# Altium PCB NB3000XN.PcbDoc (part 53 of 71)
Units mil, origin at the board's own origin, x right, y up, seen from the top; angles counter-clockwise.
Board outline 9527.56 x 6929.77 mil, 6 copper layers (Top Layer, GND+SHIELD, MidLayer1, MidLayer2, P2 - 3V3+5V0, Bottom Layer), stack 62.375 mil thick; 832 components, 1027 nets, 4655 pads, 4981 vias.
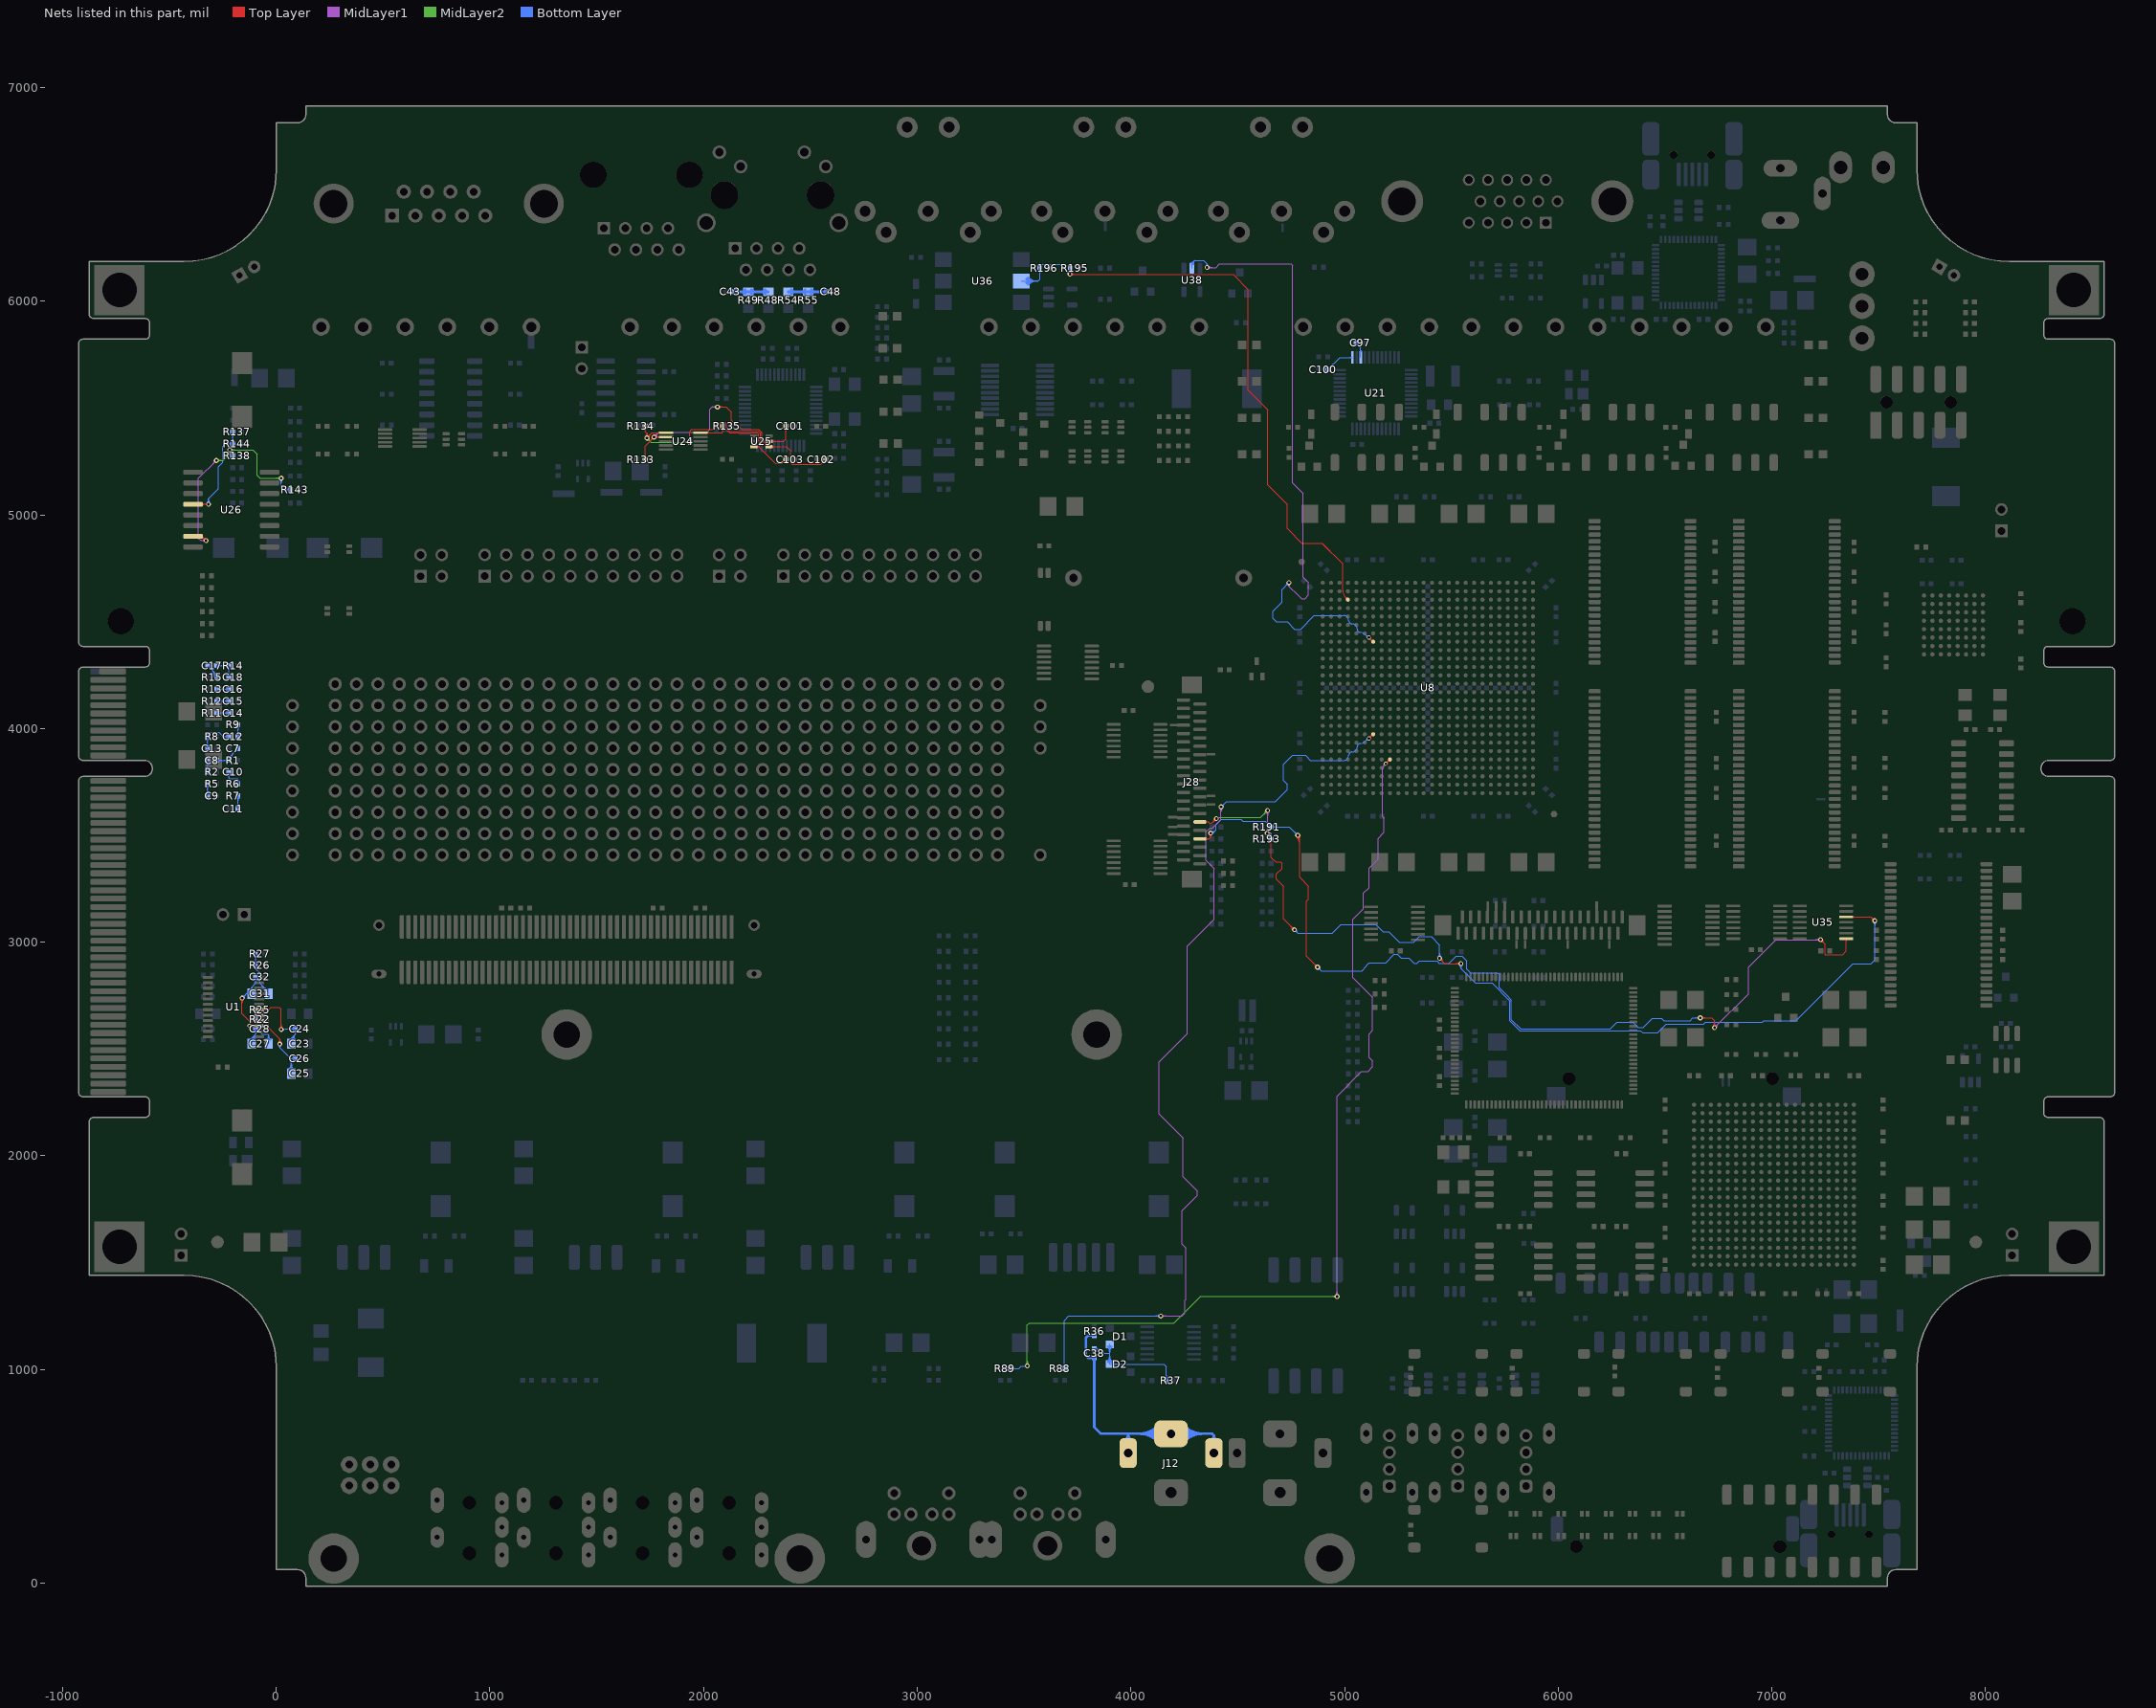
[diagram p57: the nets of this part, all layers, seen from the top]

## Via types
v1: diameter 23, hole 11.81, Top Layer to Bottom Layer, 3672 vias
v2: diameter 26, hole 11.81, Top Layer to Bottom Layer, 461 vias
v3: diameter 19, hole 11.81, Top Layer to Bottom Layer, tented both sides, 396 vias
v4: diameter 23.62, hole 11.81, Top Layer to Bottom Layer, 288 vias
v5: diameter 20, hole 11.81, Top Layer to Bottom Layer, 91 vias
v6: diameter 23, hole 11.81, Top Layer to Bottom Layer, tented both sides, 50 vias
v7: diameter 31, hole 11.81, Top Layer to Bottom Layer, 15 vias
v8: diameter 27.56, hole 11.81, Top Layer to Bottom Layer, tented both sides, 4 vias
v9: diameter 29, hole 11.81, Top Layer to Bottom Layer, 3 vias
v10: diameter 21, hole 11.81, Top Layer to Bottom Layer, 1 vias

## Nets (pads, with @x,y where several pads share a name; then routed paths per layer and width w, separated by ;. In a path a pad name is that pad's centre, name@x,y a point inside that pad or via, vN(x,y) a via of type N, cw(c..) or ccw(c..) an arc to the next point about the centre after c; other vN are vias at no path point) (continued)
LEDS#.LED7.GREEN: J28.30 R193.2 U35.12 | length 5428
  Top Layer w4: J28.30@4323.39,3562.99 4361.19,3562.99 4367.34,3556.84 4378.66,3556.84 v1(4400.52,3578.71) ; J28.30@4349.67,3558.84 cw(c4359.69,3548.81) 4359.69,3562.99 cw(c4359.69,3577.17) J28.30@4349.67,3567.15 ; v1@4391.02,3578.71 cw(c4368.09,3578.71) 4384.31,3562.49 cw(c4400.52,3546.27) v1@4400.52,3569.21 ; v1@4395.02,3578.71 cw(c4381.75,3578.71) 4391.14,3569.32 cw(c4400.52,3559.93) v1@4400.52,3573.21 ; v1@4637.52,3501.54 cw(c4637.52,3478.61) 4653.74,3494.82 cw(c4669.96,3511.04) v1@4647.02,3511.04 ; v1@4637.52,3505.54 cw(c4637.52,3492.26) 4646.91,3501.65 cw(c4656.3,3511.04) v1@4643.02,3511.04 ; v1(4637.52,3511.04) 4657.19,3491.37 4657.19,3396.73 4678.88,3375.04 4700.9,3375.04 4706.86,3369.08 4706.86,3345.37 4681.86,3320.37 4681.86,3296.04 4715.19,3262.71 4715.19,3108.37 v1(4765.19,3058.37) ; v1@4755.69,3058.37 ccw(c4732.76,3058.37) 4748.97,3074.59 ccw(c4765.19,3090.81) v1@4765.19,3067.87 ; v1@4759.69,3058.37 ccw(c4746.41,3058.37) 4755.8,3067.76 ccw(c4765.19,3077.15) v1@4765.19,3063.87 ; v1@5445,2915.5 cw(c5445,2893.02) 5460.9,2908.92 ; v1@5445,2919.5 cw(c5445,2906.68) 5454.07,2915.74 ; v1(5445,2925) 5445,2924.81 5469.77,2900.04 v1(5544.52,2900.04) ; v1@5450.5,2925 ccw(c5464.23,2925) 5454.52,2915.29 ; v1@5454.5,2925 ccw(c5477.89,2925) 5461.35,2908.46 ; v1@5537.81,2893.32 ccw(c5521.59,2877.11) 5521.59,2900.04 ccw(c5521.59,2922.98) v1@5537.81,2906.76 ; v1@5540.64,2896.15 ccw(c5531.25,2886.76) 5531.25,2900.04 ccw(c5531.25,2913.32) v1@5540.64,2903.93 ; U35.12@7348.5,3118.82 7463.75,3118.82 v1(7481.86,3100.71) ; U35.12@7377.81,3115.99 cw(c7384.64,3109.16) 7384.64,3118.82 cw(c7384.64,3128.48) U35.12@7377.81,3121.65 ; v1@7472.36,3100.71 ccw(c7449.42,3100.71) 7465.64,3116.93 ccw(c7481.86,3133.14) v1@7481.86,3110.21 ; v1@7476.36,3100.71 ccw(c7463.08,3100.71) 7472.47,3110.1 ccw(c7481.86,3119.49) v1@7481.86,3106.21
  MidLayer1 w4: v1@4630.81,3517.76 ccw(c4608.15,3540.41) 4640.19,3540.41 ; v1@4633.47,3609.99 cw(c4617.26,3593.77) 4640.19,3593.77 cw(c4663.13,3593.77) v1@4646.91,3609.99 ; v1@4633.64,3514.93 ccw(c4617.81,3530.76) 4640.19,3530.76 ; v1@4636.3,3612.82 cw(c4626.91,3603.43) 4640.19,3603.43 cw(c4653.47,3603.43) v1@4644.08,3612.82 ; v1(4637.52,3511.04) 4640.19,3513.71 v1(4640.19,3616.71) ; 4640.19,3527.54 ccw(c4654.02,3527.54) v1@4644.24,3517.76
  MidLayer2 w4: v1(4400.52,3578.71) 4405.19,3583.37 4606.86,3583.37 v1(4640.19,3616.71) ; v1@4630.69,3616.71 cw(c4607.76,3616.71) 4623.97,3600.49 cw(c4640.19,3584.27) v1@4640.19,3607.21 ; v1@4634.69,3616.71 cw(c4621.41,3616.71) 4630.8,3607.32 cw(c4640.19,3597.93) v1@4640.19,3611.21
  Bottom Layer w4: v1(4637.52,3511.04) 4654.19,3511.04 ; v1@4645.7,3506.2 cw(c4654.19,3501.17) 4654.19,3511.04 ; v1@4645.7,3515.88 ccw(c4654.19,3520.91) 4654.19,3511.04 ; R193.2@4649.59,3490.21 ccw(c4633.68,3506.12) 4656.18,3506.12 ccw(c4678.68,3506.11) R193.2@4662.77,3490.21 ; R193.2@4652.42,3487.38 ccw(c4643.34,3496.46) 4656.18,3496.46 ccw(c4669.02,3496.46) R193.2@4659.94,3487.38 ; R193.2@4656.18,3483.12 4656.18,3509.05 4654.19,3511.04 ; v1@4765.19,3048.87 cw(c4765.19,3025.94) 4781.41,3042.16 cw(c4797.63,3058.37) v1@4774.69,3058.37 ; v1@4765.19,3052.87 cw(c4765.19,3039.6) 4774.58,3048.99 cw(c4783.97,3058.37) v1@4770.69,3058.37 ; v1(4765.19,3058.37) 4781.86,3041.71 4941.9,3041.71 4983.56,3083.37 5146.54,3083.37 5179.88,3050.04 5206.86,3050.04 5256.86,3000.04 5323.52,3000.04 5341.48,3018 5349.36,3025.87 5405.77,3025.87 5445,2986.65 v1(5445,2925) ; v1@5438.28,2931.72 ccw(c5422.06,2947.93) 5445,2947.93 ccw(c5467.93,2947.93) v1@5451.72,2931.72 ; v1@5441.11,2928.89 ccw(c5431.72,2938.28) 5445,2938.28 ccw(c5458.28,2938.28) v1@5448.89,2928.89 ; v1@5537.81,2893.32 cw(c5521.59,2877.11) 5544.52,2877.11 cw(c5567.46,2877.11) v1@5551.24,2893.32 ; v1@5540.64,2896.15 cw(c5531.25,2886.76) 5544.52,2886.76 cw(c5557.8,2886.76) v1@5548.41,2896.15 ; v1(5544.52,2900.04) 5544.52,2875.48 5611.63,2808.37 5690.19,2808.37 5773.52,2725.04 5773.52,2633.37 5821.19,2585.71 6385.48,2585.71 6395.48,2575.71 6445,2575.71 6465.86,2575.71 6506.86,2616.71 6680.52,2616.71 6690.19,2626.37 6956.94,2626.37 6963.94,2633.37 7112.21,2633.37 7378.88,2900.04 7465.19,2900.04 7481.86,2916.71 v1(7481.86,3100.71) ; v1@7475.14,3093.99 cw(c7458.92,3077.77) 7481.86,3077.77 cw(c7504.79,3077.77) v1@7488.57,3093.99 ; v1@7477.97,3096.82 cw(c7468.58,3087.43) 7481.86,3087.43 cw(c7495.14,3087.43) v1@7485.75,3096.82
LEDS#.LED7.RED: J28.34 R191.2 U35.8 | length 5342.9
  Top Layer w4: J28.34@4323.39,3484.25 4365.52,3484.25 4373.52,3492.25 ; J28.34@4349.67,3480.1 cw(c4359.69,3470.07) 4359.69,3484.25 cw(c4359.69,3498.43) J28.34@4349.67,3488.41 ; v1@4367.89,3503.39 cw(c4359.7,3492.25) 4373.52,3492.25 ; v1(4373.52,3511.04) 4373.52,3492.25 ; v1@4379.16,3503.39 ccw(c4387.35,3492.25) 4373.52,3492.25 ; v1@4775.14,3493.32 cw(c4738.8,3456.99) 4790.19,3456.99 ; v1@4777.97,3496.15 cw(c4748.46,3466.64) 4790.19,3466.64 ; v1@4780.8,3498.98 cw(c4758.12,3476.3) 4790.19,3476.3 ; v1(4781.86,3500.04) 4790.19,3491.71 4790.19,3304.02 4831.52,3262.69 4831.52,3201.69 4822.86,3193.02 4822.86,2934.04 v1(4873.52,2883.37) ; v1@4783.62,3501.81 cw(c4767.78,3485.96) 4790.19,3485.96 ; v1@4864.02,2883.37 ccw(c4841.09,2883.37) 4857.31,2899.59 ccw(c4873.52,2915.81) v1@4873.52,2892.87 ; v1@4868.02,2883.37 ccw(c4854.75,2883.37) 4864.14,2892.76 ccw(c4873.52,2902.15) v1@4873.52,2888.87 ; v1(6665.19,2645.71) 6719.29,2645.71 6731.86,2633.14 v1(6731.86,2600.04) ; v1@6669.08,2641.82 cw(c6678.47,2632.43) 6678.47,2645.71 cw(c6678.47,2658.99) v1@6669.08,2649.6 ; v1@6671.91,2638.99 cw(c6688.13,2622.77) 6688.13,2645.71 cw(c6688.13,2668.64) v1@6671.91,2652.43 ; v1@6725.14,2606.76 ccw(c6708.92,2622.98) 6731.86,2622.98 ccw(c6754.79,2622.98) v1@6738.57,2606.76 ; v1@6727.97,2603.93 ccw(c6718.58,2613.32) 6731.86,2613.32 ccw(c6745.14,2613.32) v1@6735.75,2603.93 ; v1@7228.19,3002.54 cw(c7228.19,2979.61) 7244.41,2995.82 cw(c7260.63,3012.04) v1@7237.69,3012.04 ; v1@7228.19,3006.54 cw(c7228.19,2993.26) 7237.58,3002.65 cw(c7246.97,3012.04) v1@7233.69,3012.04 ; v1(7228.19,3012.04) 7248.52,2991.71 7248.52,2943.37 7250.19,2941.71 7331.86,2941.71 7348.52,2958.37 U35.8@7348.5,3016.46 ; U35.8@7345.68,3013.63 cw(c7338.8,3006.75) 7348.52,3006.75 ; 7348.52,3006.85 cw(c7358.11,3006.85) U35.8@7351.33,3013.63 ; U35.8@7348.5,3016.46 7348.52,3016.71 U35.8@7348.5,3016.46
  MidLayer1 w4: v1(6731.86,2600.04) 6890.19,2758.37 6890.19,2882.77 7019.46,3012.04 v1(7228.19,3012.04) ; v1@6731.86,2605.54 ccw(c6731.86,2618.82) 6741.25,2609.43 ccw(c6750.64,2600.04) v1@6737.36,2600.04 ; v1@6731.86,2609.54 ccw(c6731.86,2632.48) 6748.07,2616.26 ccw(c6764.29,2600.04) v1@6741.36,2600.04 ; v1@7221.47,3005.32 ccw(c7205.26,2989.11) 7205.26,3012.04 ccw(c7205.26,3034.98) v1@7221.47,3018.76 ; v1@7224.3,3008.15 ccw(c7214.91,2998.76) 7214.91,3012.04 ccw(c7214.91,3025.32) v1@7224.3,3015.93
  Bottom Layer w4: v1(4373.52,3511.04) 4384.52,3511.04 4398.52,3525.04 ; v1@4374.02,3512.46 ccw(c4378.92,3526.59) 4389.5,3516.01 ; v1@4375.33,3516.24 ccw(c4381.25,3533.29) 4394.01,3520.53 ; v1@4376.64,3520.02 ccw(c4383.57,3539.99) 4398.52,3525.04 ; 4639.43,3556.75 ccw(c4656.18,3573.5) R191.2@4656.18,3549.81 ; 4640.62,3555.56 cw(c4625.55,3540.49) R191.2@4646.86,3540.49 ; R191.2@4646.26,3549.92 ccw(c4656.18,3559.84) R191.2@4656.18,3545.81 ; R191.2@4647.45,3548.73 cw(c4639.21,3540.49) R191.2@4650.86,3540.49 ; R191.2@4659.94,3536.24 cw(c4669.02,3527.16) 4669.02,3540 cw(c4669.02,3552.84) R191.2@4659.94,3543.76 ; R191.2@4662.77,3533.41 cw(c4678.68,3517.5) 4678.68,3540 cw(c4678.68,3562.5) R191.2@4662.77,3546.59 ; v1@4772.36,3500.04 ccw(c4749.42,3500.04) 4765.64,3516.26 ccw(c4781.86,3532.48) v1@4781.86,3509.54 ; v1@4776.36,3500.04 ccw(c4763.08,3500.04) 4772.47,3509.43 ccw(c4781.86,3518.82) v1@4781.86,3505.54 ; v1(4781.86,3500.04) 4741.9,3540 R191.2@4656.18,3540 4629.47,3566.71 4523.52,3566.71 4515.19,3575.04 4423.52,3575.04 4398.52,3550.04 4398.52,3525.04 ; v1@4873.52,2873.87 cw(c4873.52,2850.94) 4889.74,2867.16 cw(c4905.96,2883.37) v1@4883.02,2883.37 ; v1@4873.52,2877.87 cw(c4873.52,2864.6) 4882.91,2873.99 cw(c4892.3,2883.37) v1@4879.02,2883.37 ; v1(4873.52,2883.37) 4890.52,2866.37 5081.56,2866.37 5102.81,2887.62 5102.81,2891.1 5114.52,2902.81 5192.62,2902.81 5232.62,2942.81 5247.38,2942.81 5265.31,2924.88 5302.27,2924.88 5325.61,2901.54 5340.11,2901.54 5350.36,2911.79 5433.46,2911.79 5443.06,2902.19 5489.36,2902.19 5522.17,2935 5550,2935 5573.19,2911.81 5573.19,2874.04 5589.86,2857.37 5716.19,2857.37 5723.52,2850.04 5723.52,2786.37 5757.18,2752.72 5781.52,2728.37 5781.52,2636.69 5824.5,2593.71 6243.19,2593.71 6274.52,2625.04 6348.52,2625.04 6373.52,2600.04 6398.52,2600.04 6441.86,2643.37 6442.69,2644.2 6484.34,2644.2 6495.5,2633.04 6617.33,2633.04 6630,2645.71 v1(6665.19,2645.71) ; v1@6658.47,2638.99 ccw(c6642.26,2622.77) 6642.26,2645.71 ccw(c6642.26,2668.64) v1@6658.47,2652.43 ; v1@6661.3,2641.82 ccw(c6651.91,2632.43) 6651.91,2645.71 ccw(c6651.91,2658.99) v1@6661.3,2649.6
LINEAOUT_L: R137.2 R144.1 U26.4 | length 757.1
  Top Layer w4: U26.4@-389.13,5050 -332.81,5050 ; U26.4@-351.46,5046 cw(c-342.13,5037.13) -342.13,5050 cw(c-342.13,5062.87) U26.4@-351.46,5054 ; U26.4@-348.56,5043.24 cw(c-332.81,5028.28) -332.81,5050 ; U26.4@-348.56,5056.76 ccw(c-332.81,5071.72) -332.81,5050 ; -332.77,5050.04 v1(-317.14,5050.04)
  Bottom Layer w4: v1@-323.86,5056.76 ccw(c-340.08,5072.98) -317.14,5072.98 ccw(c-294.21,5072.98) v1@-310.43,5056.76 ; v1@-321.03,5053.93 ccw(c-330.42,5063.32) -317.14,5063.32 ccw(c-303.86,5063.32) v1@-313.25,5053.93 ; v1(-317.14,5050.04) -317.14,5075 -270,5122.14 -270,5225 -250,5245 -250,5320 -237.42,5332.58 R144.1@-203.21,5332.58 R137.2@-203.21,5388.42 ; R144.1@-209.8,5325.99 ccw(c-225.71,5310.08) -225.71,5332.58 ccw(c-225.71,5355.08) R144.1@-209.8,5339.17 ; R144.1@-209.8,5339.66 ccw(c-225.71,5355.57) -203.21,5355.57 ccw(c-180.71,5355.57) R144.1@-196.62,5339.66 ; R137.2@-209.8,5381.33 cw(c-225.71,5365.43) -203.21,5365.43 cw(c-180.71,5365.43) R137.2@-196.62,5381.33 ; R144.1@-206.97,5328.82 ccw(c-216.05,5319.74) -216.05,5332.58 ccw(c-216.05,5345.42) R144.1@-206.97,5336.34 ; R144.1@-206.97,5336.84 ccw(c-216.05,5345.91) -203.21,5345.91 ccw(c-190.37,5345.91) R144.1@-199.45,5336.84 ; R137.2@-206.97,5384.16 cw(c-216.05,5375.08) -203.21,5375.08 cw(c-190.37,5375.08) R137.2@-199.45,5384.16
LINEAOUT_R: R138.2 R143.1 U26.7 | length 1685.2
  Top Layer w4: U26.7@-395,4900 U26.7@-389.13,4900 -348,4900 v1(-328,4880) ; U26.7@-355.67,4894.19 cw(c-355.67,4861.64) v1@-332.66,4884.66 ; U26.7@-355.67,4898.19 cw(c-355.67,4875.3) -339.49,4891.49 ; U26.7@-345.86,4900 ccw(c-340.69,4900) U26.7@-344.34,4896.34 ; v1@-337.5,4880 ccw(c-360.44,4880) -344.22,4896.22 ccw(c-328,4912.43) v1@-328,4889.5 ; v1@-333.5,4880 ccw(c-346.78,4880) -337.39,4889.39 ccw(c-328,4898.78) v1@-328,4885.5
  MidLayer1 w4: v1@-334.72,4873.28 ccw(c-350.94,4857.06) -350.94,4880 ccw(c-350.94,4902.93) v1@-334.72,4886.72 ; v1@-331.89,4876.11 ccw(c-341.28,4866.72) -341.28,4880 ccw(c-341.28,4893.28) v1@-331.89,4883.89 ; v1(-328,4880) -354,4880 -364,4890 -364,5171 v1(-280,5255) ; v1@-289.5,5255 cw(c-312.44,5255) -296.22,5238.78 cw(c-280,5222.56) v1@-280,5245.5 ; v1@-285.5,5255 cw(c-298.78,5255) -289.39,5245.61 cw(c-280,5236.22) v1@-280,5249.5
  MidLayer2 w4: v1(-280,5255) -248.14,5255 -217.81,5285.33 ; v1@-276.11,5251.11 cw(c-266.72,5241.72) -266.72,5255 cw(c-266.72,5268.28) v1@-276.11,5258.89 ; v1@-273.28,5248.28 cw(c-257.07,5232.06) -257.07,5255 cw(c-257.07,5277.93) v1@-273.28,5261.72 ; v1@-223.52,5296.78 cw(c-232.14,5285.33) -217.81,5285.33 ; v1@-213.92,5300.49 cw(c-204.53,5291.1) -204.53,5304.37 cw(c-204.53,5317.65) v1@-213.92,5308.26 ; v1@-212.1,5296.78 ccw(c-203.48,5285.33) -217.81,5285.33 ; v1@-211.09,5297.66 cw(c-194.87,5281.44) -194.87,5304.37 cw(c-194.87,5327.31) v1@-211.09,5311.09 ; v1@16.81,5164.99 ccw(c0.59,5148.77) 0.59,5171.71 ccw(c0.59,5194.64) v1@16.81,5178.43 ; v1@19.64,5167.82 ccw(c10.25,5158.43) 10.25,5171.71 ccw(c10.25,5184.99) v1@19.64,5175.6 ; v1(23.52,5171.71) -76.71,5171.71 -90,5185 -90,5284.37 -110,5304.37 v1(-217.81,5304.37) -217.81,5285.33
  Bottom Layer w4: v1@-218.11,5304.67 cw(c-241.69,5281.09) R138.2@-208.5,5277.77 ; v1(-217.81,5304.37) -203.21,5289.77 R138.2@-203.21,5276.75 ; v1@-212.14,5298.7 cw(c-230.84,5280) R138.2@-204.52,5277.37 ; -206.17,5292.73 cw(c-219.98,5278.92) R138.2@-200.54,5276.97 ; v1@16.81,5164.99 cw(c0.59,5148.77) 23.52,5148.77 cw(c46.46,5148.77) v1@30.24,5164.99 ; v1@19.64,5167.82 cw(c10.25,5158.43) 23.52,5158.43 cw(c36.8,5158.43) v1@27.41,5167.82 ; v1(23.52,5171.71) 23.52,5128.65 33.52,5118.65 R143.1@66.28,5118.65 ; R143.1@59.69,5112.06 ccw(c43.78,5096.16) 43.78,5118.65 ccw(c43.78,5141.15) R143.1@59.69,5125.24 ; R143.1@62.52,5114.89 ccw(c53.44,5105.81) 53.44,5118.65 ccw(c53.44,5131.5) R143.1@62.52,5122.41
MIDI.MIDI_RX: R195.1 R196.2 U8.C4 U36.5 | length 3637.6
  Top Layer w4: v1(3715.19,6127.37) 3717.52,6125.04 4425,6125.04 4459.96,6125.04 4478.88,6125.04 4548.52,6055.39 4548.52,5708.37 4548.52,5695 4548.52,5583.37 4640.19,5491.71 4640.19,5140.71 4731.86,5049.04 4731.86,4936.35 4800.5,4867.71 4894.79,4867.71 ; v1@3719.08,6131.26 ccw(c3734.1,6146.29) 3734.1,6125.04 ; v1@3721.91,6120.66 cw(c3732.49,6110.07) 3732.49,6125.04 ; v1@3721.91,6134.09 ccw(c3743.76,6155.94) 3743.76,6125.04 ; 4931.61,4831.02 4894.92,4867.71 4894.79,4867.71 ; 4894.79,4867.71 4896.29,4866.21 4896.42,4866.21 4992.12,4770.51 4992.12,4724.74 4992.12,4720 4992.12,4710 4992.12,4643.27 ; 4992.12,4643.27 ccw(c5030.8,4643.27) 5003.45,4615.92 ; 4992.12,4643.27 ccw(c5030.8,4643.27) 5003.45,4615.92 ; 5003.45,4615.92 cw(c4990.92,4603.39) 5008.64,4603.39 ccw(c4990.92,4603.39) 5003.45,4615.92 ; 5003.45,4615.92 ccw(c5015.98,4628.45) 5015.98,4610.73 cw(c5015.98,4628.45) 5003.45,4615.92
  Bottom Layer w4: U36.5@3487.48,6095 3565.19,6095 ; U36.5@3505.28,6083.81 cw(c3529.93,6062.24) 3529.93,6095 cw(c3529.94,6127.76) U36.5@3505.28,6106.19 ; U36.5@3508.29,6081.17 cw(c3538.75,6054.53) 3538.75,6095 cw(c3538.75,6135.47) U36.5@3508.29,6108.83 ; U36.5@3511.3,6078.54 cw(c3547.56,6046.82) 3547.56,6095 cw(c3547.56,6143.18) U36.5@3511.3,6111.46 ; U36.5@3514.31,6075.91 cw(c3556.37,6039.12) 3556.37,6095 cw(c3556.37,6150.89) U36.5@3514.31,6114.09 ; U36.5@3517.32,6073.27 cw(c3565.19,6031.41) 3565.19,6095 ; U36.5@3517.32,6116.73 ccw(c3565.19,6158.59) 3565.19,6095 ; R196.2@3567.23,6147.92 cw(c3551.32,6132.01) 3573.82,6132.01 cw(c3596.32,6132.01) R196.2@3580.41,6147.92 ; R196.2@3569.13,6163.54 ccw(c3564.37,6171.71) 3573.82,6171.71 ; R196.2@3570.06,6150.75 cw(c3560.98,6141.67) 3573.82,6141.67 cw(c3586.66,6141.67) R196.2@3577.58,6150.75 ; R196.2@3578.51,6163.54 cw(c3583.27,6171.71) 3573.82,6171.71 ; v1@3705.69,6127.37 ccw(c3682.76,6127.37) 3698.97,6143.59 ccw(c3715.19,6159.81) v1@3715.19,6136.87 ; v1@3709.69,6127.37 ccw(c3696.41,6127.37) 3705.8,6136.76 ccw(c3715.19,6146.15) v1@3715.19,6132.87 ; R195.1@3713.04,6145.79 cw(c3711.25,6141.04) 3716.32,6141.04 ; R195.1@3716.32,6155 3716.32,6141.04 ; R195.1@3719.6,6145.79 ccw(c3721.39,6141.04) 3716.32,6141.04 ; 3565.19,6095 3573.82,6103.63 3573.82,6171.71 ; 3573.82,6171.71 3575.49,6173.37 3669.19,6173.37 v1(3715.19,6127.37) 3715.19,6139.91 3716.32,6141.04
MIDI.MIDI_TX: U8.H7 U38.2 | length 3354
  Top Layer w4: v3(5114.41,4426.22) U8.H7@5134.09,4406.54 ; U8.H7@5126.59,4406.54 ccw(c5108.49,4406.54) 5121.29,4419.34 ccw(c5134.09,4432.14) U8.H7@5134.09,4414.04 ; U8.H7@5126.75,4406.54 ccw(c5109.03,4406.54) 5121.56,4419.07 ccw(c5134.09,4431.6) U8.H7@5134.09,4413.88 ; 5127.21,4413.42 ccw(c5114.41,4400.61) 5114.41,4418.72 cw(c5114.41,4400.61) 5127.21,4413.42 ; 5127.21,4413.42 cw(c5140.02,4426.22) 5121.91,4426.22 ccw(c5140.02,4426.22) 5127.21,4413.42
  MidLayer1 w4: v1(4356.86,6158.37) 4398.37,6158.37 4415.37,6175.37 4750,6175.37 ; v1@4360.75,6154.49 cw(c4370.14,6145.1) 4370.14,6158.37 cw(c4370.14,6171.65) v1@4360.75,6162.26 ; v1@4363.57,6151.66 cw(c4379.79,6135.44) 4379.79,6158.37 cw(c4379.79,6181.31) v1@4363.57,6165.09 ; v1@4735.35,4675.2 cw(c4730.32,4666.71) 4740.19,4666.71 ; v1(4740.19,4683.37) 4740.19,4666.71 ; v1@4745.03,4675.2 ccw(c4750.06,4666.71) 4740.19,4666.71 ; 4750,6175 4757.69,6167.31 4757.69,5149.21 4806.86,5100.04 4806.86,4708.37 4831.86,4683.37 4831.86,4625.04 4815.19,4608.37 4798.52,4608.37 4781.86,4625.04 4740.19,4666.71
  Bottom Layer w4: U38.2@4285.84,6155.12 U38.2@4285.84,6168.71 ; U38.2@4285.84,6168.89 U38.2@4285.84,6168.71 ; U38.2@4287.51,6169.61 cw(c4298.99,6174.52) 4290.16,6183.34 ; U38.2@4291.19,6171.18 cw(c4304.85,6177.02) 4294.34,6187.53 ; U38.2@4294.86,6172.75 cw(c4310.71,6179.52) 4298.52,6191.71 ; v1@4352.02,6166.55 ccw(c4346.99,6175.04) 4356.86,6175.04 ; v1(4356.86,6158.37) 4356.86,6175.04 ; v1@4361.7,6166.55 cw(c4366.72,6175.04) 4356.86,6175.04 ; v1@4730.69,4683.37 cw(c4707.76,4683.37) 4723.97,4667.16 cw(c4740.19,4650.94) v1@4740.19,4673.87 ; v1@4734.69,4683.37 cw(c4721.41,4683.37) 4730.8,4673.99 cw(c4740.19,4664.6) v1@4740.19,4677.87 ; v1(4740.19,4683.37) 4706.86,4650.04 4706.86,4591.71 4665.19,4550.04 4665.19,4516.71 4681.86,4500.04 4731.86,4500.04 4766.86,4465.04 4795.04,4465.04 4858.73,4528.73 4860,4528.73 4870,4528.73 4996.3,4528.73 cw(c4996.3,4504.96) 5020.07,4504.96 ccw(c5035.67,4504.96) 5035.67,4489.36 cw(c5035.67,4465.59) 5059.44,4465.59 ccw(c5075.04,4465.59) 5075.04,4449.99 cw(c5075.04,4426.22) 5091.85,4443.03 5099.58,4436.61 ; v3@5107.02,4424.92 ccw(c5089.19,4421.77) 5099.58,4436.61 ; v3@5113.11,4433.61 cw(c5109.96,4451.44) 5099.58,4436.61 ; U38.2@4285.84,6168.71 4285.52,6168.71 4285.52,6178.71 4298.52,6191.71 ; 4298.52,6191.71 4340.19,6191.71 4356.86,6175.04
MOUSE.CLOCK: R89.1 U8.AB9 | length 4861
  Top Layer w4: v3(5193.15,3835.67) U8.AB9@5212.83,3855.35 ; U8.AB9@5205.33,3855.35 cw(c5187.23,3855.35) 5200.03,3842.55 cw(c5212.83,3829.75) U8.AB9@5212.83,3847.85 ; U8.AB9@5205.49,3855.35 cw(c5187.77,3855.35) 5200.3,3842.82 cw(c5212.83,3830.29) U8.AB9@5212.83,3848.01 ; 5205.95,3848.47 cw(c5193.15,3861.28) 5193.15,3843.17 ccw(c5193.15,3861.28) 5205.95,3848.47 ; 5205.95,3848.47 ccw(c5218.76,3835.67) 5200.65,3835.67 cw(c5218.76,3835.67) 5205.95,3848.47
  MidLayer1 w4: v1@4958.47,1348.43 ccw(c4942.26,1364.64) 4965.19,1364.64 ccw(c4988.13,1364.64) v1@4971.91,1348.43 ; v1@4961.3,1345.6 ccw(c4951.91,1354.99) 4965.19,1354.99 ccw(c4978.47,1354.99) v1@4969.08,1345.6 ; v1(4965.19,1341.71) 4965.19,2279.73 5080.46,2395 5110.15,2395 5131.86,2416.71 5131.86,2443.39 5115.19,2460.06 5115.19,2569.94 5131.86,2586.61 5131.86,2741.71 5040.19,2833.37 5040.19,3107.69 5089.19,3156.69 5089.19,3230.73 5114.5,3256.04 5114.5,3346.37 5156.86,3388.73 5156.86,3486.35 5184.52,3514.02 5184.52,3581.02 5177.64,3587.9 5177.64,3660 5177.64,3670 5177.64,3718.62 5177.64,3812.16 cw(c5191.69,3812.16) 5181.76,3822.09 ; v3@5185.68,3835.02 cw(c5167.64,3833.44) 5181.51,3821.8 cw(c5195.38,3810.16) v3@5193.8,3828.2
  MidLayer2 w4: v1@3508.47,1023.43 ccw(c3492.26,1039.64) 3515.19,1039.64 ccw(c3538.13,1039.64) v1@3521.91,1023.43 ; v1@3511.3,1020.6 ccw(c3501.91,1029.99) 3515.19,1029.99 ccw(c3528.47,1029.99) v1@3519.08,1020.6 ; v1(3515.19,1016.71) 3515.19,1207.23 3525,1217.04 4202.04,1217.04 4326.71,1341.71 v1(4965.19,1341.71) ; v1@4958.47,1334.99 ccw(c4942.26,1318.77) 4942.26,1341.71 ccw(c4942.26,1364.64) v1@4958.47,1348.43 ; v1@4961.3,1337.82 ccw(c4951.91,1328.43) 4951.91,1341.71 ccw(c4951.91,1354.99) v1@4961.3,1345.6
  Bottom Layer w4: R89.1@3433.23,1005 3475,1005 3486.71,1016.71 v1(3515.19,1016.71) ; R89.1@3436.99,1001.24 cw(c3446.07,992.16) 3446.07,1005 cw(c3446.07,1017.84) R89.1@3436.99,1008.76 ; R89.1@3439.82,998.41 cw(c3455.73,982.5) 3455.73,1005 cw(c3455.73,1027.5) R89.1@3439.82,1011.59
MOUSE.DATA: R88.1 U8.W7 | length 4771.4
  Top Layer w4: v3(5114.41,3953.78) U8.W7@5134.09,3973.46 ; U8.W7@5126.59,3973.46 cw(c5108.49,3973.46) 5121.29,3960.66 cw(c5134.09,3947.86) U8.W7@5134.09,3965.96 ; U8.W7@5126.75,3973.46 cw(c5109.03,3973.46) 5121.56,3960.93 cw(c5134.09,3948.4) U8.W7@5134.09,3966.12 ; 5127.21,3966.58 cw(c5114.41,3979.39) 5114.41,3961.28 ccw(c5114.41,3979.39) 5127.21,3966.58 ; 5127.21,3966.58 ccw(c5140.02,3953.78) 5121.91,3953.78 cw(c5140.02,3953.78) 5127.21,3966.58
  MidLayer1 w4: v1(4139.96,1250.04) 4240.04,1250.04 4254,1264 4254,1324 4257.86,1327.86 4257.86,1556.54 4258,1556.69 4258,1568.19 4240.02,1586.16 4240.02,1743.96 4310.5,1814.44 4310.5,1835.56 4244,1902.06 4244,2083.31 4132.19,2195.12 4132.19,2439.67 4265.19,2572.67 4265.19,2982.41 4390.19,3107.41 4390.19,3345.71 4352.52,3383.37 4352.52,3516.71 4369.19,3533.37 4381.86,3533.37 4422.19,3573.71 v1(4422.19,3633.37) ; v1@4143.85,1246.15 cw(c4153.24,1236.76) 4153.24,1250.04 cw(c4153.24,1263.32) v1@4143.85,1253.93 ; v1@4146.68,1243.32 cw(c4162.89,1227.11) 4162.89,1250.04 cw(c4162.89,1272.98) v1@4146.68,1256.76 ; v1@4415.47,3626.66 cw(c4399.26,3610.44) 4422.19,3610.44 cw(c4445.13,3610.44) v1@4428.91,3626.66 ; v1@4418.3,3629.49 cw(c4408.91,3620.1) 4422.19,3620.1 cw(c4435.47,3620.1) v1@4426.08,3629.49
  Bottom Layer w4: R88.1@3689.13,1005 3689.13,1229.13 3710.04,1250.04 v1(4139.96,1250.04) ; v1@4133.24,1243.32 ccw(c4117.02,1227.11) 4117.02,1250.04 ccw(c4117.02,1272.98) v1@4133.24,1256.76 ; v1@4136.07,1246.15 ccw(c4126.68,1236.76) 4126.68,1250.04 ccw(c4126.68,1263.32) v1@4136.07,1253.93 ; v1(4422.19,3633.37) 4447.19,3658.37 4675.52,3658.37 4732.11,3714.96 4733.22,3716.07 4733.22,3739.34 4715.19,3757.37 4715.19,3833.37 4756.86,3875.04 4816.42,3875.04 4840.19,3851.27 4855.26,3851.27 4860,3851.27 4870,3851.27 4879.78,3851.27 4938.04,3851.27 4996.3,3851.27 ccw(c4996.3,3875.04) 5020.07,3875.04 cw(c5035.67,3875.04) 5035.67,3890.64 ccw(c5035.67,3914.41) 5059.44,3914.41 cw(c5075.04,3914.41) 5075.04,3930.01 ccw(c5075.04,3953.78) 5091.85,3936.97 5099.58,3943.39 ; v1@4422.19,3638.87 ccw(c4422.19,3652.15) 4431.58,3642.76 ccw(c4440.97,3633.37) v1@4427.69,3633.37 ; v1@4422.19,3642.87 ccw(c4422.19,3665.81) 4438.41,3649.59 ccw(c4454.63,3633.37) v1@4431.69,3633.37 ; v3@5107.02,3955.08 cw(c5089.19,3958.23) 5099.58,3943.39 ; v3@5113.11,3946.39 ccw(c5109.96,3928.56) 5099.58,3943.39
NetC7_1: C7.1 C8.2 R1.2 | length 440.8
  Bottom Layer w4: C8.2@-279.33,3851.36 R1.2@-221.18,3851.36 -221.18,3864.97 ; C8.2@-275.22,3847.25 cw(c-265.3,3837.34) -265.3,3851.36 ; C8.2@-275.22,3855.47 ccw(c-265.3,3865.39) -265.3,3851.36 ; C8.2@-272.39,3844.43 cw(c-255.65,3827.68) -255.65,3851.36 cw(c-255.64,3875.05) C8.2@-272.39,3858.3 ; R1.2@-227.77,3844.77 ccw(c-243.68,3828.87) -243.68,3851.36 ccw(c-243.68,3873.86) R1.2@-227.77,3857.95 ; R1.2@-224.94,3847.6 ccw(c-234.02,3838.52) -234.02,3851.36 ccw(c-234.02,3864.21) R1.2@-224.94,3855.12 ; R1.2@-224.24,3860.66 ccw(c-225.74,3864.97) -221.18,3864.97 ; R1.2@-223.86,3851.86 cw(c-198.68,3851.86) -216.49,3869.66 ; R1.2@-219.86,3851.86 cw(c-185.02,3851.86) -209.66,3876.49 ; R1.2@-218.12,3860.66 cw(c-216.62,3864.97) -221.18,3864.97 ; R1.2@-215.86,3851.86 cw(c-171.37,3851.86) -202.83,3883.32 ; R1.2@-211.86,3851.86 cw(c-157.71,3851.86) -196,3890.15 ; C7.1@-189.14,3906.82 cw(c-212.83,3906.82) -196.08,3890.07 cw(c-179.33,3873.32) C7.1@-179.33,3897.01 ; C7.1@-185.14,3906.82 cw(c-199.17,3906.82) -189.25,3896.9 cw(c-179.33,3886.98) C7.1@-179.33,3901.01 ; C7.1@-179.33,3906.82 -221.18,3864.97
NetC8_1: C8.1 R2.1 | length 170.4
  Bottom Layer w4: R2.1@-327.77,3802.99 ccw(c-343.68,3818.9) -321.18,3818.9 ccw(c-298.68,3818.9) R2.1@-314.59,3802.99 ; C8.1@-327.61,3844.43 cw(c-343.12,3828.91) -321.18,3828.91 ; R2.1@-324.94,3800.16 ccw(c-334.02,3809.24) -321.18,3809.24 ccw(c-308.34,3809.24) R2.1@-317.42,3800.16 ; C8.1@-324.78,3847.25 cw(c-333.46,3838.57) -321.18,3838.57 ; R2.1@-321.18,3795.91 -321.18,3850.85 C8.1@-320.67,3851.36 ; -321.18,3826.44 cw(c-295.75,3826.44) C8.1@-313.73,3844.43 ; -321.18,3836.1 cw(c-305.4,3836.1) C8.1@-316.56,3847.25
NetC9_1: C9.1 R5.1 | length 169.2
  Bottom Layer w4: R5.1@-327.77,3733.37 cw(c-343.68,3717.46) -321.18,3717.46 cw(c-298.68,3717.47) R5.1@-314.59,3733.37 ; C9.1@-327.54,3692 ccw(c-343.6,3708.37) -320.67,3708.37 ; R5.1@-324.94,3736.2 cw(c-334.02,3727.12) -321.18,3727.12 cw(c-308.34,3727.12) R5.1@-317.42,3736.2 ; C9.1@-324.74,3689.15 ccw(c-334.25,3698.84) -320.67,3698.84 ccw(c-307.08,3698.84) C9.1@-316.6,3689.15 ; R5.1@-321.18,3740.45 -321.18,3708.89 -320.67,3708.37 ; C9.1@-320.67,3685 -320.67,3708.37 ; C9.1@-313.8,3692 cw(c-297.73,3708.37) -320.67,3708.37
NetC10_1: C10.1 R6.1 | length 209.5
  Bottom Layer w4: C10.1@-227.61,3788.97 cw(c-244.36,3772.22) -220.67,3772.22 cw(c-196.98,3772.22) C10.1@-213.73,3788.97 ; C10.1@-224.78,3791.8 cw(c-234.7,3781.88) -220.67,3781.88 cw(c-206.64,3781.88) C10.1@-216.56,3791.8 ; C10.1@-220.67,3795.91 -220.67,3768.2 -218.73,3766.27 -181.27,3766.27 -178.82,3763.82 R6.1@-178.82,3740.45 ; R6.1@-185.41,3747.54 ccw(c-201.32,3763.44) -178.82,3763.44 ccw(c-156.32,3763.44) R6.1@-172.23,3747.54 ; R6.1@-182.58,3744.71 ccw(c-191.66,3753.79) -178.82,3753.79 ccw(c-165.98,3753.79) R6.1@-175.06,3744.71
NetC11_1: C11.1 R7.1 | length 175
  Bottom Layer w4: C11.1@-186.27,3631.94 ccw(c-204.25,3649.92) -178.82,3649.92 ; R7.1@-185.41,3677.92 cw(c-201.32,3662.01) -178.82,3662.01 cw(c-156.32,3662.01) R7.1@-172.23,3677.92 ; C11.1@-183.44,3629.11 ccw(c-194.6,3640.26) -178.82,3640.26 ; R7.1@-182.58,3680.75 cw(c-191.66,3671.67) -178.82,3671.67 cw(c-165.98,3671.67) R7.1@-175.06,3680.75 ; C11.1@-179.33,3625 -178.82,3625.51 R7.1@-178.82,3685 ; -178.82,3637.79 ccw(c-166.54,3637.79) C11.1@-175.22,3629.11 ; -178.82,3647.45 ccw(c-156.88,3647.45) C11.1@-172.39,3631.94
NetC12_1: C12.1 R9.1 | length 133.7
  Bottom Layer w4: R9.1@-185.41,4010.65 cw(c-201.32,3994.74) -178.82,3994.74 cw(c-156.32,3994.74) R9.1@-172.23,4010.65 ; C12.1@-184.56,3970.58 ccw(c-190.51,3980.04) -179.33,3980.04 ; R9.1@-182.58,4013.47 cw(c-191.66,4004.39) -178.82,4004.39 cw(c-165.98,4004.39) R9.1@-175.06,4013.47 ; C12.1@-179.33,3962.27 -179.33,3980.04 ; R9.1@-178.82,4017.73 -178.82,3980.55 -179.33,3980.04 ; C12.1@-174.1,3970.58 cw(c-168.15,3980.04) -179.33,3980.04
NetC12_2: C12.2 C13.1 R8.2 | length 399
  Bottom Layer w4: R8.2@-327.77,3955.19 cw(c-343.68,3939.28) -321.18,3939.28 cw(c-298.68,3939.28) R8.2@-314.59,3955.19 ; C13.1@-327.61,3913.76 ccw(c-343.12,3929.27) -321.18,3929.27 ; R8.2@-324.94,3958.02 cw(c-334.02,3948.94) -321.18,3948.94 cw(c-308.34,3948.94) R8.2@-317.42,3958.02 ; C13.1@-324.78,3910.93 ccw(c-333.46,3919.61) -321.18,3919.61 ; -321.18,3922.08 ccw(c-305.41,3922.08) C13.1@-316.56,3910.93 ; -321.18,3931.74 ccw(c-295.75,3931.74) C13.1@-313.73,3913.76 ; C13.1@-320.67,3906.82 -321.18,3907.33 R8.2@-321.18,3962.27 -321.18,3970.38 -308.19,3983.37 ; R8.2@-319.93,3963.18 cw(c-309.7,3966.61) -317.33,3974.23 ; R8.2@-316.14,3964.45 cw(c-302.85,3968.9) -312.76,3978.8 ; R8.2@-312.34,3965.72 cw(c-296,3971.19) -308.19,3983.37 ; C12.2@-227.61,3955.34 ccw(c-244.35,3938.59) -244.35,3962.27 ccw(c-244.36,3985.96) C12.2@-227.61,3969.21 ; C12.2@-224.78,3958.16 ccw(c-234.7,3948.25) -234.7,3962.27 ccw(c-234.7,3976.3) C12.2@-224.78,3966.38 ; C12.2@-220.67,3962.27 -247.04,3962.27 -268.14,3983.37 -308.19,3983.37
NetC14_1: C14.1 R11.1 | length 172.9
  Bottom Layer w4: R11.1@-278.82,4073.18 C14.1@-220.67,4073.18 ; R11.1@-275.06,4069.42 cw(c-265.98,4060.34) -265.98,4073.18 cw(c-265.98,4086.02) R11.1@-275.06,4076.94 ; R11.1@-272.23,4066.59 cw(c-256.32,4050.69) -256.32,4073.18 cw(c-256.32,4095.68) R11.1@-272.23,4079.77 ; C14.1@-227.61,4066.24 ccw(c-244.35,4049.5) -244.35,4073.18 ccw(c-244.36,4096.87) C14.1@-227.61,4080.12 ; C14.1@-224.78,4069.07 ccw(c-234.7,4059.15) -234.7,4073.18 ccw(c-234.7,4087.21) C14.1@-224.78,4077.29
NetC15_1: C15.1 R12.1 | length 172.9
  Bottom Layer w4: R12.1@-278.82,4128.64 C15.1@-220.67,4128.64 ; R12.1@-275.06,4124.87 cw(c-265.98,4115.8) -265.98,4128.64 cw(c-265.98,4141.48) R12.1@-275.06,4132.4 ; R12.1@-272.23,4122.05 cw(c-256.32,4106.14) -256.32,4128.64 cw(c-256.32,4151.13) R12.1@-272.23,4135.23 ; C15.1@-227.61,4121.7 ccw(c-244.35,4104.95) -244.35,4128.64 ccw(c-244.36,4152.32) C15.1@-227.61,4135.57 ; C15.1@-224.78,4124.53 ccw(c-234.7,4114.61) -234.7,4128.64 ccw(c-234.7,4142.67) C15.1@-224.78,4132.75
NetC16_1: C16.1 R13.1 | length 172.9
  Bottom Layer w4: R13.1@-278.82,4184.09 C16.1@-220.67,4184.09 ; R13.1@-275.06,4180.33 cw(c-265.98,4171.25) -265.98,4184.09 cw(c-265.98,4196.93) R13.1@-275.06,4187.85 ; R13.1@-272.23,4177.5 cw(c-256.32,4161.59) -256.32,4184.09 cw(c-256.32,4206.59) R13.1@-272.23,4190.68 ; C16.1@-227.61,4177.15 ccw(c-244.35,4160.41) -244.35,4184.09 ccw(c-244.36,4207.78) C16.1@-227.61,4191.03 ; C16.1@-224.78,4179.98 ccw(c-234.7,4170.06) -234.7,4184.09 ccw(c-234.7,4198.12) C16.1@-224.78,4188.2
NetC17_1: C17.1 R15.1 | length 267.9
  Bottom Layer w4: C17.1@-320.67,4285.19 cw(c-320.67,4261.5) -303.92,4278.25 cw(c-287.17,4295) C17.1@-310.86,4295 ; C17.1@-320.67,4289.19 cw(c-320.67,4275.16) -310.75,4285.08 cw(c-300.83,4295) C17.1@-314.86,4295 ; C17.1@-320.67,4295 -278.82,4253.15 ; -304,4278.33 cw(c-342.29,4240.04) R15.1@-288.14,4240.04 ; -297.17,4271.5 cw(c-328.63,4240.04) R15.1@-284.14,4240.04 ; -290.34,4264.67 cw(c-314.98,4240.04) R15.1@-280.14,4240.04 ; -283.51,4257.84 cw(c-301.32,4240.04) R15.1@-276.14,4240.04 ; R15.1@-281.88,4248.84 ccw(c-283.38,4253.15) -278.82,4253.15 ; R15.1@-278.82,4239.55 -278.82,4253.15 ; R15.1@-275.76,4248.84 cw(c-274.25,4253.15) -278.82,4253.15
NetC17_2: C17.2 C18.1 R14.2 | length 305.9
  Bottom Layer w4: C17.2@-279.33,4295 R14.2@-221.18,4295 -221.18,4257.55 -220.67,4257.04 ; C17.2@-275.22,4290.89 cw(c-265.3,4280.97) -265.3,4295 ; C17.2@-275.22,4299.11 ccw(c-265.3,4309.03) -265.3,4295 ; C17.2@-272.39,4288.06 cw(c-255.65,4271.32) -255.65,4295 cw(c-255.64,4318.69) C17.2@-272.39,4301.94 ; R14.2@-227.77,4287.92 cw(c-243.68,4272.01) -221.18,4272.01 cw(c-198.68,4272.01) R14.2@-214.59,4287.92 ; R14.2@-227.77,4288.41 ccw(c-243.68,4272.5) -243.68,4295 ccw(c-243.68,4317.5) R14.2@-227.77,4301.59 ; C18.1@-225.79,4247.92 ccw(c-231.36,4257.04) -220.67,4257.04 ; R14.2@-224.94,4290.75 cw(c-234.02,4281.67) -221.18,4281.67 cw(c-208.34,4281.67) R14.2@-217.42,4290.75 ; R14.2@-224.94,4291.24 ccw(c-234.02,4282.16) -234.02,4295 ccw(c-234.02,4307.84) R14.2@-224.94,4298.76 ; C18.1@-220.67,4239.55 -220.67,4257.04 ; C18.1@-215.55,4247.92 cw(c-209.98,4257.04) -220.67,4257.04
NetC23_1: C23.1 C24.2 U1.18 | length 714.1
  Top Layer w4: U1.18@-79.84,2683.82 -35,2683.82 -23.82,2695 15,2695 23.52,2686.48 v1(23.52,2591.71) ; U1.18@-60.1,2680.22 cw(c-51.42,2671.54) -51.42,2683.82 cw(c-51.42,2696.1) U1.18@-60.1,2687.42 ; v1@16.81,2598.43 ccw(c0.59,2614.64) 23.52,2614.64 ccw(c46.46,2614.64) v1@30.24,2598.43 ; v1@19.64,2595.6 ccw(c10.25,2604.99) 23.52,2604.99 ccw(c36.8,2604.99) v1@27.41,2595.6
  Bottom Layer w4: v1(23.52,2591.71) 38.86,2591.71 42.15,2595 C24.2@89.33,2595 89.33,2568.74 ; C23.1@68.65,2528.72 cw(c83.99,2538.03) 71.31,2550.72 ; C23.1@70.63,2525 70.63,2550.04 89.33,2568.74 ; C23.1@72.07,2530.8 cw(c88.48,2540.75) 74.91,2554.32 ; C23.1@75.49,2532.87 cw(c92.97,2543.47) 78.52,2557.93 ; C23.1@78.91,2534.94 cw(c97.46,2546.19) 82.12,2561.53 ; C23.1@82.33,2537.02 cw(c101.95,2548.91) 85.73,2565.14 ; C24.2@82.39,2601.94 cw(c65.64,2618.69) 65.64,2595 cw(c65.65,2571.31) 82.39,2588.06 cw(c65.64,2571.31) 89.33,2571.31 cw(c113.02,2571.32) C24.2@96.27,2588.06 ; C24.2@85.22,2599.11 cw(c75.3,2609.03) 75.3,2595 cw(c75.3,2580.97) 85.22,2590.89 cw(c75.3,2580.97) 89.33,2580.97 cw(c103.36,2580.97) C24.2@93.44,2590.89 ; C23.1@85.75,2539.09 cw(c106.44,2551.64) 89.33,2568.74
NetC25_1: C25.1 C26.1 U1.17 | length 646.4
  Top Layer w4: U1.17@-79.84,2658.62 -43.43,2658.62 -34.81,2650 -34.81,2600 16.86,2548.33 v1(16.86,2523.37) ; U1.17@-60.1,2655.03 cw(c-51.42,2646.34) -51.42,2658.62 cw(c-51.42,2670.9) U1.17@-60.1,2662.22 ; v1@10.14,2530.09 ccw(c-6.08,2546.31) 16.86,2546.31 ccw(c39.79,2546.31) v1@23.57,2530.09 ; v1@12.97,2527.26 ccw(c3.58,2536.65) 16.86,2536.65 ccw(c30.14,2536.65) v1@20.75,2527.26
  Bottom Layer w4: v1@12.32,2515.03 cw(c8.18,2507.4) 16.86,2507.4 ; v1(16.86,2523.37) 16.86,2507.4 ; v1@21.39,2515.03 ccw(c25.53,2507.4) 16.86,2507.4 ; C25.1@58.12,2403.06 ccw(c27.93,2433.25) 70.63,2433.25 ccw(c113.32,2433.25) C25.1@83.14,2403.06 ; C25.1@60.95,2400.23 ccw(c37.59,2423.59) 70.63,2423.59 ccw(c103.67,2423.59) C25.1@80.31,2400.23 ; C25.1@63.78,2397.4 ccw(c47.25,2413.93) 70.63,2413.93 ccw(c94.01,2413.93) C25.1@77.48,2397.4 ; C25.1@70.63,2385.63 70.63,2453.63 ; C26.1@80.76,2450.85 ccw(c72.63,2446.32) 72.63,2455.63 ; C26.1@80.76,2460.41 cw(c72.63,2464.94) 72.63,2455.63 ; C26.1@89.33,2455.63 72.63,2455.63 ; 16.86,2507.4 70.63,2453.63 ; 70.63,2453.63 72.63,2455.63
NetC27_1: C27.1 C28.1 U1.15 | length 505.3
  Top Layer w4: v1@-124.33,2608.23 U1.15@-79.84,2608.23 ; v1@-120.59,2604.49 cw(c-111.55,2595.45) -111.55,2608.23 ; v1@-120.59,2612.26 ccw(c-110.84,2622.01) -110.84,2608.23 ; v1@-117.76,2601.66 cw(c-101.9,2585.79) U1.15@-101.9,2608.23 ; v1@-117.76,2615.09 ccw(c-101.19,2631.66) U1.15@-101.19,2608.23 ; U1.15@-99.58,2604.63 ccw(c-108.26,2595.95) -108.26,2608.23 ccw(c-108.27,2620.51) U1.15@-99.58,2611.83
  Bottom Layer w4: v1(-124.48,2608.37) -109.04,2608.37 ; C27.1@-117.68,2547.29 ccw(c-118.45,2551.3) -114.37,2551.3 ; C27.1@-116.34,2528.71 cw(c-100.16,2538.65) -113.59,2552.08 ; C27.1@-114.37,2525 -114.37,2551.3 ; C27.1@-112.93,2530.8 cw(c-95.72,2541.38) -110.01,2555.66 ; C27.1@-111.06,2547.29 cw(c-110.29,2551.3) -114.37,2551.3 ; C27.1@-109.53,2532.9 cw(c-91.28,2544.11) -106.42,2559.25 ; C27.1@-106.12,2534.99 cw(c-86.84,2546.83) -102.84,2562.83 ; C28.1@-105.34,2596.68 ccw(c-118.47,2598.95) -109.04,2608.37 ; C27.1@-102.71,2537.08 cw(c-82.4,2549.56) -99.25,2566.42 ; C28.1@-102.61,2588.06 cw(c-119.36,2571.31) -95.67,2571.31 cw(c-71.98,2571.31) C28.1@-88.73,2588.06 ; C28.1@-99.78,2590.89 cw(c-109.7,2580.97) -95.67,2580.97 cw(c-81.64,2580.97) C28.1@-91.56,2590.89 ; C27.1@-99.3,2539.18 cw(c-77.96,2552.29) -95.67,2570 ; C28.1@-97.34,2604.67 cw(c-99.62,2617.8) -109.04,2608.37 ; -114.37,2551.3 -95.67,2570 C28.1@-95.67,2595 -109.04,2608.37
NetC27_2: C27.2 R22.2 R25.2 | length 476.4
  Bottom Layer w4: R22.2@-102.77,2647.08 ccw(c-118.68,2662.99) -96.18,2662.99 ccw(c-73.68,2662.99) R22.2@-89.59,2647.08 ; R25.2@-102.77,2677.92 cw(c-118.68,2662.01) -96.18,2662.01 cw(c-73.68,2662.01) R25.2@-89.59,2677.92 ; R22.2@-99.94,2644.25 ccw(c-109.02,2653.33) -96.18,2653.33 ccw(c-83.34,2653.33) R22.2@-92.42,2644.25 ; R25.2@-99.94,2680.75 cw(c-109.02,2671.67) -96.18,2671.67 cw(c-83.34,2671.67) R25.2@-92.42,2680.75 ; R22.2@-98.72,2640.38 ccw(c-87.06,2636.36) -95.78,2627.64 ; R25.2@-96.18,2685 R22.2@-96.18,2640 -96.18,2628.04 -76.48,2608.34 -76.48,2580 -66.48,2570 -40,2570 -35.63,2565.63 ; R22.2@-94.93,2639.08 ccw(c-80.33,2634.04) -91.26,2623.12 ; R22.2@-91.15,2637.77 ccw(c-73.61,2631.72) -86.73,2618.59 ; R22.2@-87.37,2636.47 ccw(c-66.88,2629.4) -82.21,2614.07 ; C27.2@-46.35,2543.99 ccw(c-62.83,2565.63) -35.63,2565.63 ; C27.2@-43.92,2540.81 ccw(c-56.68,2557.55) -35.63,2557.55 ccw(c-14.58,2557.55) C27.2@-27.34,2540.81 ; C27.2@-35.63,2525 -35.63,2565.63 ; C27.2@-24.91,2543.99 cw(c-8.43,2565.63) -35.63,2565.63
NetC31_1: C31.1 C32.1 U1.16 | length 548.5
  Top Layer w4: v1@-166.53,2731.66 cw(c-182.74,2715.44) -159.81,2715.44 cw(c-136.87,2715.44) v1@-153.09,2731.66 ; v1@-163.7,2734.49 cw(c-173.09,2725.1) -159.81,2725.1 cw(c-146.53,2725.1) v1@-155.92,2734.49 ; v1(-159.81,2738.37) -159.81,2665.37 -127.86,2633.42 U1.16@-79.84,2633.43 ; U1.16@-99.58,2629.83 ccw(c-108.26,2621.15) -108.26,2633.42 ccw(c-108.27,2645.71) U1.16@-99.58,2637.02
  Bottom Layer w4: v1(-159.81,2738.37) -138.18,2760 ; v1@-159.81,2743.87 ccw(c-159.81,2757.15) -150.42,2747.76 ccw(c-141.03,2738.37) v1@-154.31,2738.37 ; v1@-159.81,2747.87 ccw(c-159.81,2770.81) -143.59,2754.59 ccw(c-127.37,2738.37) v1@-150.31,2738.37 ; C31.1@-131.3,2754.89 ccw(c-138.18,2752.81) -138.18,2760 ; C31.1@-131.3,2765.11 cw(c-138.18,2767.19) -138.18,2760 ; C31.1@-120.33,2781.57 ccw(c-123.37,2790.04) -114.37,2790.04 ; C31.1@-114.37,2760 -138.18,2760 ; C31.1@-108.41,2781.57 cw(c-105.37,2790.04) -114.37,2790.04 ; C32.1@-102.61,2830.56 cw(c-119.36,2813.81) -95.67,2813.81 cw(c-71.98,2813.82) C32.1@-88.73,2830.56 ; C32.1@-99.78,2833.39 cw(c-109.7,2823.47) -95.67,2823.47 cw(c-81.64,2823.47) C32.1@-91.56,2833.39 ; C32.1@-95.67,2837.5 -95.67,2808.74 -114.37,2790.04 ; -138.18,2760 -126.28,2771.91 -114.37,2783.81 -114.37,2790.04
NetC31_2: C31.2 R26.2 R27.2 | length 495.2
  Bottom Layer w4: R26.2@-102.77,2898.33 ccw(c-118.68,2914.24) -96.18,2914.24 ccw(c-73.68,2914.24) R26.2@-89.59,2898.33 ; R27.2@-102.77,2937.92 cw(c-118.68,2922.01) -96.18,2922.01 cw(c-73.68,2922.01) R27.2@-89.59,2937.92 ; R26.2@-100.65,2882.58 cw(c-104.77,2875.04) -96.18,2875.04 ; R26.2@-99.94,2895.5 ccw(c-109.02,2904.58) -96.18,2904.58 ccw(c-83.34,2904.58) R26.2@-92.42,2895.5 ; R27.2@-99.94,2940.75 cw(c-109.02,2931.67) -96.18,2931.67 cw(c-83.34,2931.67) R27.2@-92.42,2940.75 ; R27.2@-96.18,2945 R26.2@-96.18,2891.25 -96.18,2875.04 ; R26.2@-91.71,2882.58 ccw(c-87.59,2875.04) -96.18,2875.04 ; -66.32,2796.32 cw(c-97.72,2764.92) C31.2@-53.31,2764.92 ; -64.61,2794.61 ccw(c-35.63,2823.59) C31.2@-35.63,2782.61 ; -59.49,2789.49 cw(c-84.06,2764.92) C31.2@-49.31,2764.92 ; -57.78,2787.78 ccw(c-35.63,2809.93) C31.2@-35.63,2778.61 ; C31.2@-52.66,2782.66 cw(c-70.41,2764.92) C31.2@-45.31,2764.92 ; C31.2@-50.95,2780.95 ccw(c-35.63,2796.28) C31.2@-35.63,2774.61 ; C31.2@-35.63,2760 -35.63,2765.63 -76.48,2806.48 -76.48,2855.34 -96.18,2875.04
NetC38_1: C38.1 J12.2 J12.3 J12.4 R36.1 | length 2397.9
  Bottom Layer w12: R36.1@3829,1158.82 3798.82,1158.82 3790,1150 3790,1065 3800.67,1054.33 C38.1@3829,1054.33 3829,800 3829,730 3859.61,699.39 3989.39,699.39 ; J12.3@3970.43,668.42 ccw(c3954.13,697.19) 3987.19,697.19 ; J12.3@3987.19,608.84 3987.19,697.19 ; J12.3@4003.95,668.42 cw(c4020.26,697.19) 3987.19,697.19 ; J12.4@4131.93,659.09 ccw(c4034.64,561.8) 4034.64,699.39 ccw(c4034.64,836.98) J12.4@4131.93,739.69 ; J12.4@4140.42,667.58 ccw(c4063.61,590.77) 4063.61,699.39 ccw(c4063.61,808.01) J12.4@4140.42,731.21 ; J12.4@4148.9,676.06 ccw(c4092.58,619.74) 4092.58,699.39 ccw(c4092.58,779.04) J12.4@4148.9,722.72 ; J12.4@4193.52,699.39 J12.4@4187.98,699.39 ; J12.4@4227.06,676.06 cw(c4283.38,619.74) 4283.38,699.39 cw(c4283.38,779.04) J12.4@4227.06,722.72 ; J12.4@4235.54,667.58 cw(c4312.35,590.77) 4312.35,699.39 cw(c4312.35,808.01) J12.4@4235.54,731.21 ; J12.4@4244.03,659.09 cw(c4341.32,561.8) 4341.32,699.39 cw(c4341.32,836.98) J12.4@4244.03,739.69 ; J12.2@4374.92,669.89 ccw(c4365.4,691.23) 4388.77,691.23 ; J12.2@4388.77,608.84 4388.77,691.23 ; J12.2@4402.61,669.89 cw(c4412.13,691.23) 4388.77,691.23 ; 3987.19,697.19 3989.39,699.39 ; 3989.39,699.39 4015,699.39 J12.4@4187.98,699.39 ; J12.4@4187.98,699.39 4380.61,699.39 4388.77,691.23
NetC38_2: C38.2 D1.1 D2.3 R37.2 | length 1022.6
  Bottom Layer w4: C38.2@3829,1095.67 3854.33,1095.67 3875,1075 3900.79,1075 ; C38.2@3833.11,1091.56 cw(c3843.03,1081.64) 3843.03,1095.67 cw(c3843.03,1109.7) C38.2@3833.11,1099.78 ; C38.2@3835.94,1088.73 cw(c3852.69,1071.98) 3852.69,1095.67 cw(c3852.69,1119.36) C38.2@3835.94,1102.61 ; D2.3@3889.67,1036.11 ccw(c3862.84,1062.94) 3900.79,1062.94 ccw(c3938.73,1062.94) D2.3@3911.9,1036.11 ; D1.1@3889.67,1106.49 cw(c3862.84,1079.66) 3900.79,1079.66 cw(c3938.73,1079.65) D1.1@3911.9,1106.49 ; D2.3@3892.5,1033.28 ccw(c3872.5,1053.29) 3900.79,1053.29 ccw(c3929.07,1053.29) D2.3@3909.07,1033.28 ; D1.1@3892.5,1109.31 cw(c3872.5,1089.31) 3900.79,1089.31 cw(c3929.07,1089.31) D1.1@3909.07,1109.31 ; D2.3@3895.33,1030.46 ccw(c3882.16,1043.63) 3900.79,1043.63 ccw(c3919.42,1043.63) D2.3@3906.24,1030.46 ; D1.1@3895.33,1112.14 cw(c3882.16,1098.97) 3900.79,1098.97 cw(c3919.42,1098.97) D1.1@3906.24,1112.14 ; D1.1@3900.79,1117.6 3900.79,1075 ; D2.3@3907.23,1019.54 cw(c3920.4,1006.37) 3920.4,1025 cw(c3920.4,1043.63) D2.3@3907.23,1030.46 ; D2.3@3910.06,1016.72 cw(c3930.06,996.71) 3930.06,1025 cw(c3930.06,1053.29) D2.3@3910.06,1033.28 ; D2.3@3912.88,1013.89 cw(c3939.71,987.06) 3939.71,1025 cw(c3939.72,1062.94) D2.3@3912.88,1036.11 ; R37.2@4159.91,956.08 ccw(c4144,971.99) 4166.5,971.99 ccw(c4189,971.99) R37.2@4173.09,956.08 ; R37.2@4162.74,953.25 ccw(c4153.66,962.33) 4166.5,962.33 ccw(c4179.34,962.33) R37.2@4170.26,953.25 ; R37.2@4166.5,949 4166.5,1013.5 4155,1025 D2.3@3900.79,1025 3900.79,1075
NetC43_1: C43.1 R48.2 R49.2 | length 335.6
  Bottom Layer w4: C43.1@2145.67,6045 C43.1@2146.3,6044.37
  Bottom Layer w12: C43.1@2146.3,6044.37 R49.2@2210,6044.37 R48.2@2303.31,6044.37 ; C43.1@2149.78,6040.89 cw(c2158.18,6032.49) 2158.18,6044.37 ; C43.1@2149.78,6049.11 ccw(c2161.22,6060.55) 2161.22,6044.37 ; R49.2@2195.4,6034.69 ccw(c2172.04,6011.33) 2172.04,6044.37 ccw(c2172.04,6077.41) R49.2@2195.4,6054.05 ; R49.2@2224.6,6034.69 cw(c2247.96,6011.33) 2247.96,6044.37 cw(c2247.96,6077.41) R49.2@2224.6,6054.05 ; R48.2@2288.71,6034.69 ccw(c2265.35,6011.33) 2265.35,6044.37 ccw(c2265.35,6077.41) R48.2@2288.71,6054.05
NetC48_2: C48.2 R54.1 R55.1 | length 357.7
  Bottom Layer w4: C48.2@2568.7,6044.37 2571.83,6047.5 C48.2@2574.33,6050
  Bottom Layer w12: R54.1@2396.69,6044.37 R55.1@2490,6044.37 C48.2@2568.7,6044.37 ; R54.1@2411.29,6034.69 cw(c2434.65,6011.33) 2434.65,6044.37 cw(c2434.65,6077.41) R54.1@2411.29,6054.05 ; R55.1@2475.4,6034.69 ccw(c2452.04,6011.33) 2452.04,6044.37 ccw(c2452.04,6077.41) R55.1@2475.4,6054.05 ; R55.1@2504.6,6034.69 cw(c2527.96,6011.33) 2527.96,6044.37 cw(c2527.96,6077.41) R55.1@2504.6,6054.05 ; 2558.78,6044.37 ccw(c2558.78,6060.55) C48.2@2570.22,6049.11 ; 2561.82,6044.37 cw(c2561.82,6032.49) C48.2@2570.22,6040.89
NetC97_2: C97.2 U21.39 | length 151.1
  Bottom Layer w4: C97.2@5054.33,5795.19 cw(c5054.33,5771.5) 5071.08,5788.25 cw(c5087.83,5805) C97.2@5064.14,5805 ; C97.2@5054.33,5799.19 cw(c5054.33,5785.16) 5064.25,5795.08 cw(c5074.17,5805) C97.2@5060.14,5805 ; C97.2@5054.33,5805 5076.1,5783.23 U21.39@5076.1,5737.32 ; U21.39@5073.27,5763.68 ccw(c5066.45,5770.51) 5076.1,5770.51 ccw(c5085.76,5770.51) U21.39@5078.93,5763.68
NetC100_1: C100.1 U21.37 | length 214.2
  Bottom Layer w4: C100.1@4920.67,5680 4977.99,5737.32 U21.37@5036.73,5737.32 ; C100.1@4920.67,5685.81 ccw(c4920.67,5699.84) 4930.59,5689.92 ccw(c4940.51,5680) C100.1@4926.48,5680 ; C100.1@4920.67,5689.81 ccw(c4920.67,5713.5) 4937.42,5696.75 ccw(c4954.17,5680) C100.1@4930.48,5680 ; U21.37@5033.9,5734.49 ccw(c5027.08,5727.67) 5027.08,5737.32 ccw(c5027.08,5746.98) U21.37@5033.9,5740.15
NetC101_1: C101.1 R133.2 U24.7 U25.5 | length 1544.9
  Top Layer w4: R133.2@1720.46,5267.08 ccw(c1704.55,5282.99) 1727.05,5282.99 ccw(c1749.54,5282.99) R133.2@1733.64,5267.08 ; R133.2@1723.29,5264.25 ccw(c1714.21,5273.33) 1727.05,5273.33 ccw(c1739.89,5273.33) R133.2@1730.81,5264.25 ; R133.2@1727.05,5260 1727.05,5322.94 v4(1768.8,5364.68) U24.7@1824.29,5364.68 ; v4@1758.99,5364.68 cw(c1735.3,5364.68) 1752.05,5347.94 cw(c1768.8,5331.19) v4@1768.8,5354.87 ; v4@1762.99,5364.68 cw(c1748.96,5364.68) 1758.88,5354.76 cw(c1768.8,5344.84) v4@1768.8,5358.87 ; v4@1772.91,5360.58 cw(c1782.83,5350.66) 1782.83,5364.68 cw(c1782.83,5378.71) v4@1772.91,5368.79 ; v4@1775.73,5357.75 cw(c1792.48,5341) 1792.48,5364.68 cw(c1792.48,5388.37) v4@1775.73,5371.62 ; U24.7@1794,5361.86 ccw(c1787.17,5355.03) 1787.17,5364.68 ccw(c1787.17,5374.34) U24.7@1794,5367.51 ; v4(2065,5505) 2105.19,5505 2130.19,5480 2130.19,5443.24 2140.62,5432.81 2145.85,5432.81 2178.79,5399.87 2258.54,5399.87 2273.73,5384.68 2273.73,5356.27 2285.59,5344.41 ; v4@2069.11,5500.89 cw(c2079.03,5490.97) 2079.03,5505 cw(c2079.03,5519.03) v4@2069.11,5509.11 ; v4@2071.94,5498.06 cw(c2088.69,5481.31) 2088.69,5505 cw(c2088.69,5528.69) v4@2071.94,5511.94 ; U25.5@2294.65,5340.43 ccw(c2285.59,5332.1) 2285.59,5344.41 ; U25.5@2294.65,5348.39 cw(c2285.59,5356.72) 2285.59,5344.41 ; U25.5@2320.85,5340.26 cw(c2330.87,5330.23) 2330.87,5344.41 cw(c2330.88,5358.59) U25.5@2320.85,5348.56 ; C101.1@2378.26,5408.06 cw(c2361.51,5391.31) 2385.2,5391.31 cw(c2408.88,5391.32) C101.1@2392.13,5408.06 ; C101.1@2381.09,5410.89 cw(c2371.17,5400.97) 2385.2,5400.97 cw(c2399.22,5400.97) C101.1@2389.31,5410.89 ; C101.1@2385.2,5415 2385.2,5356.08 2373.53,5344.41 U25.5@2307.83,5344.41 2285.59,5344.41
  MidLayer1 w4: v4(1768.8,5364.68) 1791.92,5387.81 2017.81,5387.81 2030,5400 2030,5495 2040,5505 v4(2065,5505) ; v4@1768.8,5370.5 ccw(c1768.8,5384.52) 1778.72,5374.6 ccw(c1788.64,5364.68) v4@1774.61,5364.68 ; v4@1768.8,5374.5 ccw(c1768.8,5398.18) 1785.55,5381.43 ccw(c1802.29,5364.68) v4@1778.61,5364.68 ; v4@2058.06,5498.06 ccw(c2041.31,5481.31) 2041.31,5505 ccw(c2041.31,5528.69) v4@2058.06,5511.94 ; v4@2060.89,5500.89 ccw(c2050.97,5490.97) 2050.97,5505 ccw(c2050.97,5519.03) v4@2060.89,5509.11
NetC102_1: C102.1 R134.2 U24.6 U25.4 | length 1681.8
  Top Layer w4: R134.2@1720.66,5407.72 cw(c1706.78,5392.95) 1727.05,5392.95 cw(c1747.31,5392.95) R134.2@1733.43,5407.72 ; R134.2@1723.4,5410.63 cw(c1715.48,5402.21) 1727.05,5402.21 cw(c1738.61,5402.21) R134.2@1730.69,5410.63 ; R134.2@1727.05,5415 1727.05,5390 1735,5382.05 ; v4@1728.43,5367.29 ccw(c1715.14,5382.05) 1735,5382.05 ; v4@1731.11,5364.32 ccw(c1723.23,5373.06) 1735,5373.06 ccw(c1746.77,5373.06) v4@1738.89,5364.32 ; v4@1735,5365.81 ccw(c1735,5379.84) 1744.92,5369.92 ccw(c1754.84,5360) v4@1740.81,5360 ; v4@1735,5369.81 ccw(c1735,5393.5) 1751.75,5376.75 ccw(c1768.5,5360) v4@1744.81,5360 ; v4@1741.57,5367.29 cw(c1754.86,5382.05) 1735,5382.05 ; U24.6@1794,5381.54 ccw(c1787.17,5374.71) 1787.17,5384.37 ccw(c1787.17,5394.03) U24.6@1794,5387.2 ; U24.6@1824.29,5384.37 1759.37,5384.37 v4(1735,5360) 1735,5382.05 ; v4@1928.06,5346.94 ccw(c1911.31,5363.69) 1935,5363.69 ccw(c1958.69,5363.69) v4@1941.94,5346.94 ; v4@1930.89,5344.11 ccw(c1920.97,5354.03) 1935,5354.03 ccw(c1949.03,5354.03) v4@1939.11,5344.11 ; v4(1935,5340) 1935,5390 1945,5400 2043.07,5400 2072.37,5429.29 2075.88,5432.81 2103.49,5432.81 2107,5429.3 2107,5408.43 2123.56,5391.87 2255.22,5391.87 2265.73,5381.37 2265.73,5352.95 2299.87,5318.82 U25.4@2307.83,5318.82 2388.08,5318.82 2406.86,5300.04 2406.86,5245.71 2414.86,5237.71 2549.24,5237.71 C102.1@2571.54,5260 ; 2288.32,5330.37 cw(c2276.77,5318.82) U25.4@2293.1,5318.82 ; 2290.47,5328.22 ccw(c2298.98,5336.72) U25.4@2298.98,5324.69 ; U25.4@2320.85,5314.67 cw(c2330.87,5304.64) 2330.87,5318.82 cw(c2330.87,5333) U25.4@2320.85,5322.97 ; C102.1@2561.72,5260 cw(c2538.04,5260) 2554.79,5243.25 cw(c2571.54,5226.5) C102.1@2571.54,5250.19 ; C102.1@2565.72,5260 cw(c2551.7,5260) 2561.62,5250.08 cw(c2571.54,5240.16) C102.1@2571.54,5254.19
  MidLayer2 w4: v4@1735,5350.19 cw(c1735,5326.5) 1751.75,5343.25 cw(c1768.5,5360) v4@1744.81,5360 ; v4@1735,5354.19 cw(c1735,5340.16) 1744.92,5350.08 cw(c1754.84,5360) v4@1740.81,5360 ; v4(1735,5360) 1755,5340 v4(1935,5340) ; v4@1928.06,5333.06 ccw(c1911.31,5316.31) 1911.31,5340 ccw(c1911.31,5363.69) v4@1928.06,5346.94 ; v4@1930.89,5335.89 ccw(c1920.97,5325.97) 1920.97,5340 ccw(c1920.97,5354.03) v4@1930.89,5344.11
NetC103_1: C103.1 R135.2 U24.5 U25.3 | length 722.7
  Top Layer w4: U24.5@1985.71,5384.37 2089.69,5384.39 R135.2@2089.68,5415 2099,5405.68 2099,5405.11 2120.24,5383.87 2251.91,5383.87 2257.73,5378.05 2257.73,5349.64 2265.19,5342.18 2265.19,5327.04 2257.97,5319.82 ; U24.5@2016,5381.54 cw(c2022.84,5374.7) 2022.84,5384.38 cw(c2022.82,5394.02) U24.5@2016,5387.2 ; R135.2@2083.1,5407.92 cw(c2067.19,5392.01) 2089.69,5392.01 cw(c2112.18,5392.01) R135.2@2096.27,5407.92 ; R135.2@2085.92,5410.75 cw(c2076.84,5401.67) 2089.69,5401.67 cw(c2102.53,5401.67) R135.2@2093.45,5410.75 ; U25.3@2235,5318.82 2256.97,5318.82 ; U25.3@2248.24,5314.91 cw(c2256.97,5307.13) 2256.97,5318.82 ; U25.3@2248.24,5322.73 ccw(c2256.97,5330.51) 2256.97,5318.82 ; 2368.45,5243.25 ccw(c2351.7,5260) C103.1@2375.39,5260 ; 2368.45,5243.25 cw(c2385.2,5226.5) C103.1@2385.2,5250.19 ; C103.1@2379.39,5260 cw(c2365.35,5260) 2375.28,5250.08 cw(c2385.2,5240.16) C103.1@2385.2,5254.19 ; C103.1@2385.2,5260 2366.91,5241.71 2336.08,5241.71 2257.97,5319.82 ; 2256.97,5318.82 2257.97,5319.82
